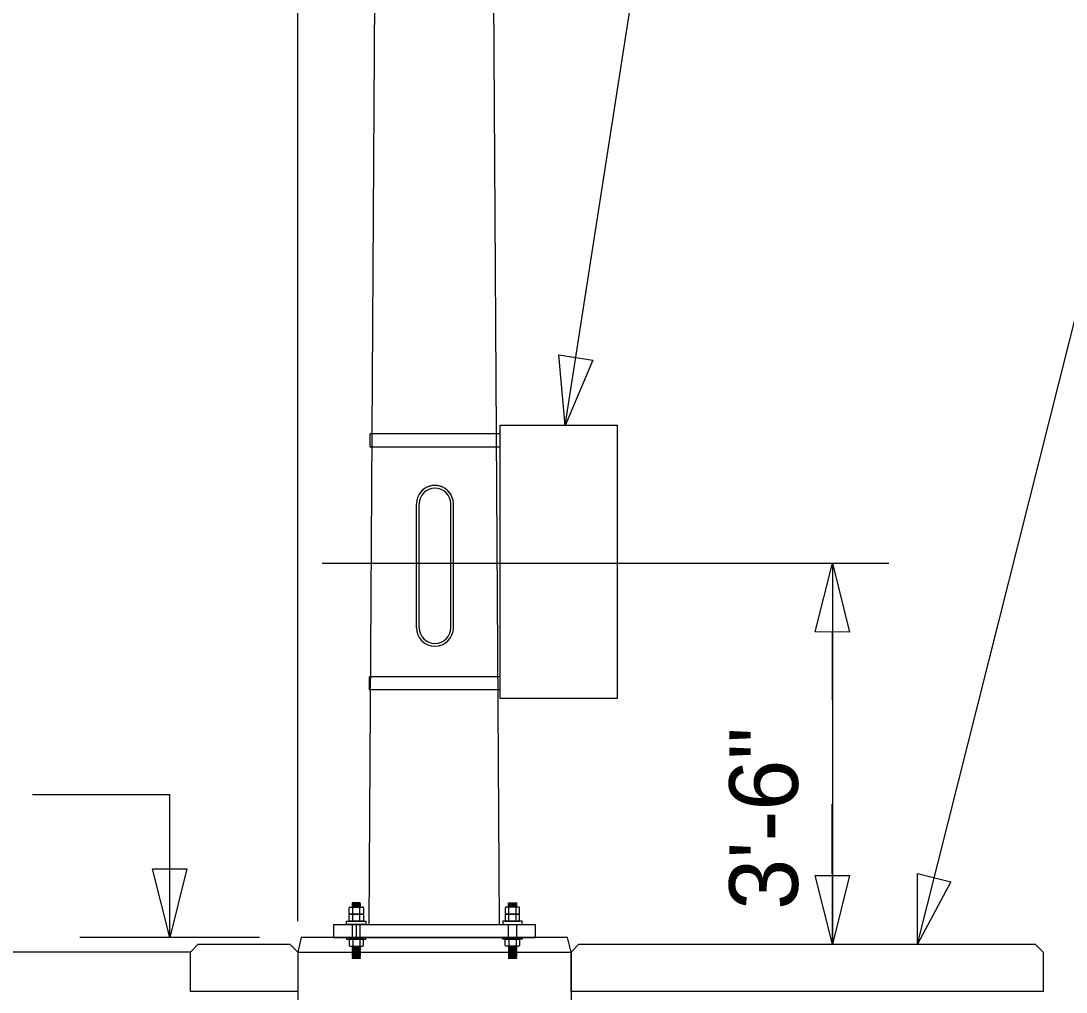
# Model space of a CAD drawing. Extents: x 1299104.8 to 1299141.6, y 239639.8 to 239661.8.
# Drawn here: x 1299115.274 to 1299117.1, y 239644.27 to 239645.968 of the extents above; entities that cross this region are included whole.
import ezdxf

# ---------------------------------------------------------------- set-up
doc = ezdxf.new("R2010")
doc.units = 0
for name, color, linetype in [('DIM TXT', 7, 'Continuous'), ('Level 3', 7, 'Continuous'), ('Level 4', 7, 'Continuous'), ('Level 7', 7, 'Continuous'), ('Level 8', 7, 'Continuous')]:
    doc.layers.add(name, color=color, linetype=linetype)

msp = doc.modelspace()

# ---------------------------------------------------------------- linework, layer by layer
at = {"layer": 'Level 3'}
for p, q in [((1299115.883, 239644.3884), (1299115.9399, 239653.9384)), ((1299116.1104, 239644.3884), (1299116.0535, 239653.9384)), ((1299115.8846, 239645.2229), (1299115.8847, 239645.2457)), ((1299116.1115, 239645.2457), (1299115.8847, 239645.2457)), ((1299116.1115, 239645.2229), (1299115.8846, 239645.2229)), ((1299115.9653, 239644.9071), (1299115.9653, 239645.1235)), ((1299115.97, 239644.9071), (1299115.97, 239645.1235)), ((1299116.0253, 239644.9071), (1299116.0253, 239645.1235)), ((1299116.03, 239644.9071), (1299116.03, 239645.1235)), ((1299115.8832, 239644.7983), (1299115.8833, 239644.8211)), ((1299116.1115, 239644.8211), (1299115.8833, 239644.8211)), ((1299116.1115, 239644.7983), (1299115.8832, 239644.7983)), ((1299115.8205, 239644.3884), (1299115.8205, 239644.3656)), ((1299115.8205, 239644.3884), (1299116.1729, 239644.3884)), ((1299116.1729, 239644.3884), (1299116.1729, 239644.3656)), ((1299115.8205, 239644.3656), (1299116.1729, 239644.3656)), ((1299115.5705, 239644.34), (1299115.5842, 239644.3538)), ((1299115.5842, 239644.3538), (1299115.7442, 239644.3538)), ((1299115.7442, 239644.3538), (1299115.758, 239644.34)), ((1299116.2355, 239644.34), (1299116.2492, 239644.3538)), ((1299116.2492, 239644.3538), (1299117.0467, 239644.3538)), ((1299117.0467, 239644.3538), (1299117.0605, 239644.34)), ((1299115.5705, 239644.34), (1299115.1945, 239644.34)), ((1299115.5705, 239644.2713), (1299115.5705, 239644.34)), ((1299115.758, 239644.34), (1299116.2355, 239644.34)), ((1299115.758, 239644.34), (1299115.758, 239643.3509)), ((1299115.758, 239644.34), (1299115.758, 239644.2713)), ((1299116.2355, 239644.34), (1299116.2355, 239643.3509)), ((1299116.2355, 239644.2713), (1299116.2355, 239644.34)), ((1299117.0605, 239644.34), (1299117.0605, 239644.2713)), ((1299115.758, 239644.2713), (1299115.5705, 239644.2713)), ((1299117.0605, 239644.2713), (1299116.2355, 239644.2713))]:
    msp.add_line(p, q, dxfattribs=at)
for points in [[(1299116.1115, 239645.2609), (1299116.3162, 239645.2609), (1299116.3162, 239644.7834), (1299116.1115, 239644.7834)], [(1299116.2291, 239644.3656), (1299115.7643, 239644.3656), (1299115.758, 239644.34), (1299116.2355, 239644.34)]]:
    msp.add_lwpolyline(points, close=True, dxfattribs=at)
for centre, radius, start, end in [((1299115.9977, 239645.1235), 0.0323, 0, 180), ((1299115.9977, 239645.1235), 0.0323, 22.6224, 157.3776), ((1299115.9977, 239645.1235), 0.0276, 0, 180), ((1299115.9977, 239644.9071), 0.0323, 180, 360), ((1299115.9977, 239644.9071), 0.0276, 180, 360)]:
    msp.add_arc(centre, radius, start, end, dxfattribs=at)
at = {"layer": 'Level 4'}
for p, q in [((1299115.8493, 239644.4189), (1299115.8713, 239644.4189)), ((1299115.8541, 239644.4065), (1299115.8541, 239644.4189)), ((1299115.8665, 239644.4065), (1299115.8665, 239644.4189)), ((1299116.1441, 239644.4189), (1299116.1222, 239644.4189)), ((1299116.1269, 239644.4065), (1299116.1269, 239644.4189)), ((1299116.1394, 239644.4065), (1299116.1394, 239644.4189)), ((1299115.8478, 239644.4065), (1299115.8478, 239644.4175)), ((1299115.8727, 239644.4065), (1299115.8478, 239644.4065)), ((1299115.8478, 239644.394), (1299115.8478, 239644.405)), ((1299115.8493, 239644.4065), (1299115.8713, 239644.4065)), ((1299115.8541, 239644.394), (1299115.8541, 239644.4065)), ((1299115.8665, 239644.394), (1299115.8665, 239644.4065)), ((1299115.8727, 239644.4175), (1299115.8727, 239644.4065)), ((1299115.8727, 239644.405), (1299115.8727, 239644.394)), ((1299116.1207, 239644.4175), (1299116.1207, 239644.4065)), ((1299116.1207, 239644.4065), (1299116.1456, 239644.4065)), ((1299116.1207, 239644.405), (1299116.1207, 239644.394)), ((1299116.1441, 239644.4065), (1299116.1222, 239644.4065)), ((1299116.1269, 239644.394), (1299116.1269, 239644.4065)), ((1299116.1394, 239644.394), (1299116.1394, 239644.4065)), ((1299116.1456, 239644.4065), (1299116.1456, 239644.4175)), ((1299116.1456, 239644.394), (1299116.1456, 239644.405)), ((1299115.8727, 239644.394), (1299115.8478, 239644.394)), ((1299115.8603, 239644.3884), (1299115.8603, 239644.3656)), ((1299116.1207, 239644.394), (1299116.1456, 239644.394)), ((1299115.8727, 239644.3628), (1299115.8478, 239644.3628)), ((1299115.8478, 239644.3628), (1299115.8478, 239644.3518)), ((1299115.8493, 239644.3503), (1299115.8713, 239644.3503)), ((1299115.8541, 239644.3628), (1299115.8541, 239644.3503)), ((1299115.8665, 239644.3628), (1299115.8665, 239644.3503)), ((1299115.8727, 239644.3518), (1299115.8727, 239644.3628)), ((1299116.1207, 239644.3518), (1299116.1207, 239644.3628)), ((1299116.1207, 239644.3628), (1299116.1456, 239644.3628)), ((1299116.1441, 239644.3503), (1299116.1222, 239644.3503)), ((1299116.1269, 239644.3628), (1299116.1269, 239644.3503)), ((1299116.1394, 239644.3628), (1299116.1394, 239644.3503)), ((1299116.1456, 239644.3628), (1299116.1456, 239644.3518))]:
    msp.add_line(p, q, dxfattribs=at)
for points in [[(1299115.8674, 239644.4189), (1299115.8674, 239644.426), (1299115.8532, 239644.426), (1299115.8532, 239644.4189)], [(1299115.8532, 239644.426), (1299115.8674, 239644.426), (1299115.8532, 239644.4253), (1299115.8532, 239644.4246), (1299115.8674, 239644.4253), (1299115.8674, 239644.4246), (1299115.8532, 239644.4239), (1299115.8532, 239644.4232), (1299115.8674, 239644.4239), (1299115.8674, 239644.4232), (1299115.8532, 239644.4225), (1299115.8532, 239644.4217), (1299115.8674, 239644.4225), (1299115.8674, 239644.4217), (1299115.8532, 239644.421), (1299115.8532, 239644.4203), (1299115.8674, 239644.421), (1299115.8674, 239644.4203), (1299115.8532, 239644.4196), (1299115.8532, 239644.4189), (1299115.8674, 239644.4196), (1299115.8674, 239644.4189)], [(1299116.126, 239644.4189), (1299116.126, 239644.426), (1299116.1402, 239644.426), (1299116.1402, 239644.4189)], [(1299116.126, 239644.426), (1299116.1402, 239644.426), (1299116.126, 239644.4253), (1299116.126, 239644.4246), (1299116.1402, 239644.4253), (1299116.1402, 239644.4246), (1299116.126, 239644.4239), (1299116.126, 239644.4232), (1299116.1402, 239644.4239), (1299116.1402, 239644.4232), (1299116.126, 239644.4225), (1299116.126, 239644.4217), (1299116.1402, 239644.4225), (1299116.1402, 239644.4217), (1299116.126, 239644.421), (1299116.126, 239644.4203), (1299116.1402, 239644.421), (1299116.1402, 239644.4203), (1299116.126, 239644.4196), (1299116.126, 239644.4189), (1299116.1402, 239644.4196), (1299116.1402, 239644.4189)], [(1299115.8674, 239644.3656), (1299115.8674, 239644.3884), (1299115.8532, 239644.3884), (1299115.8532, 239644.3656)], [(1299116.126, 239644.3656), (1299116.126, 239644.3884), (1299116.1402, 239644.3884), (1299116.1402, 239644.3656)], [(1299115.8532, 239644.3503), (1299115.8674, 239644.3503), (1299115.8532, 239644.3496), (1299115.8532, 239644.3489), (1299115.8674, 239644.3496), (1299115.8674, 239644.3489), (1299115.8532, 239644.3482), (1299115.8532, 239644.3475), (1299115.8674, 239644.3482), (1299115.8674, 239644.3475), (1299115.8532, 239644.3468), (1299115.8532, 239644.3461), (1299115.8674, 239644.3468), (1299115.8674, 239644.3461), (1299115.8532, 239644.3454), (1299115.8532, 239644.3447), (1299115.8674, 239644.3454), (1299115.8674, 239644.3447), (1299115.8532, 239644.3439), (1299115.8532, 239644.3432), (1299115.8674, 239644.3439), (1299115.8674, 239644.3432), (1299115.8532, 239644.3425), (1299115.8532, 239644.3418), (1299115.8674, 239644.3425), (1299115.8674, 239644.3418), (1299115.8532, 239644.3411), (1299115.8532, 239644.3404), (1299115.8674, 239644.3411), (1299115.8674, 239644.3404), (1299115.8532, 239644.3397), (1299115.8532, 239644.339), (1299115.8674, 239644.3397), (1299115.8674, 239644.339), (1299115.8532, 239644.3383), (1299115.8532, 239644.3375), (1299115.8674, 239644.3383), (1299115.8674, 239644.3375), (1299115.8532, 239644.3368), (1299115.8532, 239644.3361), (1299115.8674, 239644.3368), (1299115.8674, 239644.3361), (1299115.8532, 239644.3354), (1299115.8532, 239644.3347), (1299115.8674, 239644.3354), (1299115.8674, 239644.3347), (1299115.8532, 239644.334), (1299115.8532, 239644.3333), (1299115.8674, 239644.334), (1299115.8674, 239644.3333), (1299115.8532, 239644.3326), (1299115.8532, 239644.3319), (1299115.8674, 239644.3326), (1299115.8674, 239644.3319), (1299115.8532, 239644.3312), (1299115.8532, 239644.3304), (1299115.8674, 239644.3312), (1299115.8674, 239644.3304), (1299115.8532, 239644.3297), (1299115.8532, 239644.329), (1299115.8674, 239644.3297), (1299115.8674, 239644.329)], [(1299116.126, 239644.3503), (1299116.1402, 239644.3503), (1299116.126, 239644.3496), (1299116.126, 239644.3489), (1299116.1402, 239644.3496), (1299116.1402, 239644.3489), (1299116.126, 239644.3482), (1299116.126, 239644.3475), (1299116.1402, 239644.3482), (1299116.1402, 239644.3475), (1299116.126, 239644.3468), (1299116.126, 239644.3461), (1299116.1402, 239644.3468), (1299116.1402, 239644.3461), (1299116.126, 239644.3454), (1299116.126, 239644.3447), (1299116.1402, 239644.3454), (1299116.1402, 239644.3447), (1299116.126, 239644.3439), (1299116.126, 239644.3432), (1299116.1402, 239644.3439), (1299116.1402, 239644.3432), (1299116.126, 239644.3425), (1299116.126, 239644.3418), (1299116.1402, 239644.3425), (1299116.1402, 239644.3418), (1299116.126, 239644.3411), (1299116.126, 239644.3404), (1299116.1402, 239644.3411), (1299116.1402, 239644.3404), (1299116.126, 239644.3397), (1299116.126, 239644.339), (1299116.1402, 239644.3397), (1299116.1402, 239644.339), (1299116.126, 239644.3383), (1299116.126, 239644.3375), (1299116.1402, 239644.3383), (1299116.1402, 239644.3375), (1299116.126, 239644.3368), (1299116.126, 239644.3361), (1299116.1402, 239644.3368), (1299116.1402, 239644.3361), (1299116.126, 239644.3354), (1299116.126, 239644.3347), (1299116.1402, 239644.3354), (1299116.1402, 239644.3347), (1299116.126, 239644.334), (1299116.126, 239644.3333), (1299116.1402, 239644.334), (1299116.1402, 239644.3333), (1299116.126, 239644.3326), (1299116.126, 239644.3319), (1299116.1402, 239644.3326), (1299116.1402, 239644.3319), (1299116.126, 239644.3312), (1299116.126, 239644.3304), (1299116.1402, 239644.3312), (1299116.1402, 239644.3304), (1299116.126, 239644.3297), (1299116.126, 239644.329), (1299116.1402, 239644.3297), (1299116.1402, 239644.329)]]:
    msp.add_lwpolyline(points, dxfattribs=at)
for points in [[(1299115.8773, 239644.3884), (1299115.8432, 239644.3884), (1299115.8432, 239644.394), (1299115.8773, 239644.394)], [(1299116.1161, 239644.3884), (1299116.1502, 239644.3884), (1299116.1502, 239644.394), (1299116.1161, 239644.394)], [(1299115.8773, 239644.3656), (1299115.8432, 239644.3656), (1299115.8432, 239644.3628), (1299115.8773, 239644.3628)], [(1299116.1161, 239644.3656), (1299116.1502, 239644.3656), (1299116.1502, 239644.3628), (1299116.1161, 239644.3628)]]:
    msp.add_lwpolyline(points, close=True, dxfattribs=at)
for centre, start, end in [((1299115.8493, 239644.4175), 90, 180), ((1299115.8526, 239644.4175), 0, 90), ((1299115.8679, 239644.4175), 90, 180), ((1299115.8713, 239644.4175), 0, 90), ((1299116.1222, 239644.4175), 90, 180), ((1299116.1255, 239644.4175), 0, 90), ((1299116.1408, 239644.4175), 90, 180), ((1299116.1441, 239644.4175), 0, 90), ((1299115.8493, 239644.405), 90, 180), ((1299115.8526, 239644.405), 360, 90), ((1299115.8679, 239644.405), 90, 180), ((1299115.8713, 239644.405), 0, 90), ((1299116.1222, 239644.405), 90, 180), ((1299116.1255, 239644.405), 360, 90), ((1299116.1408, 239644.405), 90, 180), ((1299116.1441, 239644.405), 0, 90), ((1299115.8493, 239644.3518), 180, 270), ((1299115.8526, 239644.3518), 270, 0), ((1299115.8679, 239644.3518), 180, 270), ((1299115.8713, 239644.3518), 270, 360), ((1299116.1222, 239644.3518), 180, 270), ((1299116.1255, 239644.3518), 270, 0), ((1299116.1408, 239644.3518), 180, 270), ((1299116.1441, 239644.3518), 270, 360)]:
    msp.add_arc(centre, 0.00145, start, end, dxfattribs=at)
for centre, major_axis, start_param, end_param in [((1299115.8581, 239644.4175), (-0.00401, 0), 4.712389, 6.283185), ((1299115.8625, 239644.4175), (0.00401, 0), 0, 1.570796), ((1299116.1309, 239644.4175), (-0.00401, 0), 4.712389, 6.283185), ((1299116.1353, 239644.4175), (0.00401, 0), 0, 1.570796), ((1299115.8581, 239644.405), (-0.00401, 0), 4.712389, 6.283185), ((1299115.8625, 239644.405), (0.00401, 0), 0, 1.570796), ((1299116.1309, 239644.405), (-0.00401, 0), 4.712389, 6.283185), ((1299116.1353, 239644.405), (0.00401, 0), 0, 1.570796), ((1299115.8581, 239644.3518), (-0.00401, 0), 0, 1.570796), ((1299115.8625, 239644.3518), (0.00401, 0), 4.712389, 6.283185), ((1299116.1309, 239644.3518), (-0.00401, 0), 0, 1.570796), ((1299116.1353, 239644.3518), (0.00401, 0), 4.712389, 6.283185)]:
    msp.add_ellipse(centre, major_axis=major_axis, ratio=0.362172, start_param=start_param, end_param=end_param, dxfattribs=at)
at = {"layer": 'Level 7'}
msp.add_line((1299115.801, 239645.0196), (1299116.7907, 239645.0196), dxfattribs=at)
at = {"layer": 'Level 8'}
for p, q in [((1299115.758, 239644.394), (1299115.758, 239648.6921)), ((1299116.2254, 239645.2608), (1299116.5298, 239647.2173)), ((1299116.8407, 239644.3538), (1299117.2211, 239645.8648)), ((1299116.6922, 239645.0196), (1299116.6919, 239644.7805)), ((1299116.6922, 239645.0196), (1299116.6922, 239644.3538)), ((1299115.2944, 239644.6156), (1299115.5344, 239644.6156)), ((1299115.5344, 239644.3656), (1299115.5344, 239644.6156)), ((1299116.6922, 239644.3538), (1299116.692, 239644.5989)), ((1299115.6912, 239644.3656), (1299115.3776, 239644.3656))]:
    msp.add_line(p, q, dxfattribs=at)
for points in [[(1299116.2735, 239645.3748), (1299116.2254, 239645.2608), (1299116.2142, 239645.384)], [(1299116.662, 239644.8996), (1299116.6922, 239645.0196), (1299116.722, 239644.8995)], [(1299115.5644, 239644.4856), (1299115.5344, 239644.3656), (1299115.5044, 239644.4856)], [(1299116.7221, 239644.4738), (1299116.6922, 239644.3538), (1299116.6621, 239644.4738)], [(1299116.8991, 239644.4628), (1299116.8407, 239644.3538), (1299116.8409, 239644.4775)]]:
    msp.add_lwpolyline(points, close=True, dxfattribs=at)

# ---------------------------------------------------------------- texts
at = {"layer": 'DIM TXT'}
msp.add_text('3\'-6"', height=0.12, rotation=90, dxfattribs=at).set_placement((1299116.6319, 239644.4139))

doc.saveas('drawing.dxf')
